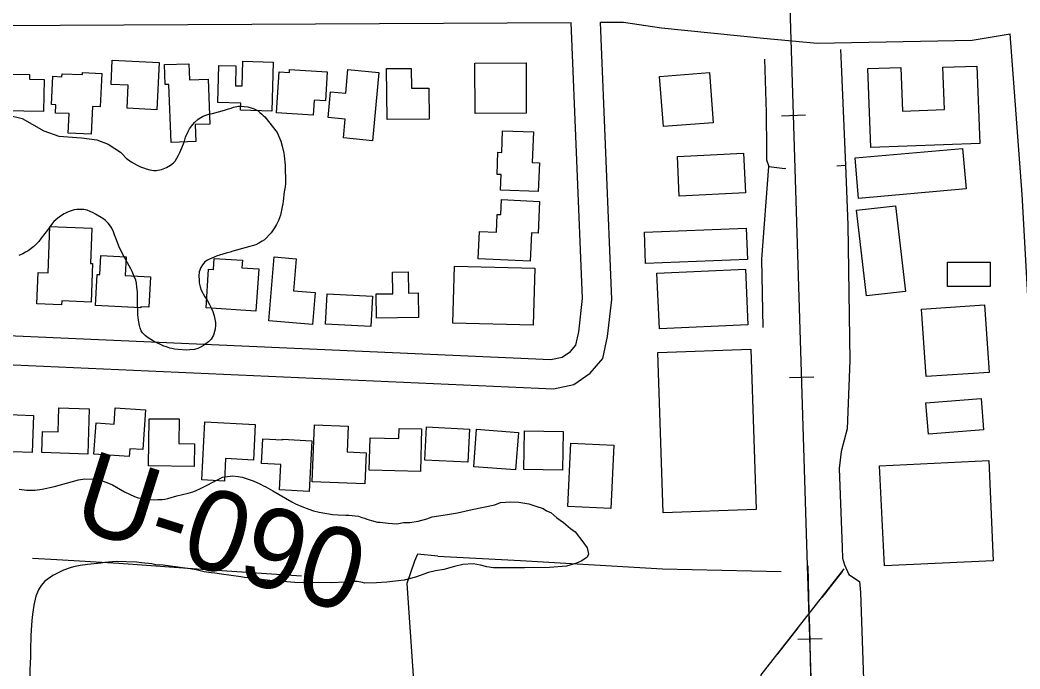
# Model space of a CAD drawing. Extents: x 3297716 to 3335574, y 688621 to 713991.
# Drawn here: x 3325465 to 3326496, y 697434 to 698103 of the extents above; entities that cross this region are included whole.
import ezdxf

# ---------------------------------------------------------------- set-up
doc = ezdxf.new("R2010")
doc.units = 0
for name, color, linetype in [('V-BLDG-OTLN', 7, 'Continuous'), ('V-RAIL-TRAK', 7, 'Continuous'), ('V-RIVR-RANG-IDEN', 7, 'Continuous'), ('V-ROAD-CNTR', 7, 'Continuous'), ('V-SITE-VEGE', 7, 'Continuous'), ('V-TOPO-SHOR', 7, 'Continuous'), ('V-UTIL-LINE', 7, 'Continuous')]:
    doc.layers.add(name, color=color, linetype=linetype)

msp = doc.modelspace()

# ---------------------------------------------------------------- linework, layer by layer
at = {"layer": 'V-BLDG-OTLN'}
for points in [[(3325559.8, 698061.9), (3325608.2, 698059.5), (3325605.8, 698010.7), (3325575, 698012.2), (3325576.1, 698035.9), (3325558.6, 698036.8)], [(3325660.3, 697995.9), (3325645.3, 697995.4), (3325645.9, 697977.8), (3325620.5, 697976.9), (3325618.2, 698036.7), (3325614.4, 698036.6), (3325613.6, 698057.2), (3325638.7, 698058.2), (3325639.4, 698041.4), (3325658.6, 698042.1)], [(3325725.6, 698059.9), (3325724.2, 698009.2), (3325692, 698010.1), (3325692.2, 698017.6), (3325668.7, 698018.3), (3325669.8, 698056.5), (3325687.3, 698056), (3325686.7, 698035.5), (3325693.7, 698035.3), (3325694.5, 698060.8)], [(3325933.8, 698058.7), (3325986.5, 698059), (3325986.8, 698007.3), (3325934.1, 698007)], [(3325548.9, 698048.1), (3325547.4, 698013.8), (3325539.3, 698014.2), (3325537.9, 697985.5), (3325514.4, 697986.5), (3325515.3, 698006.7), (3325501.1, 698007.3), (3325501.5, 698015.8), (3325497.1, 698016), (3325498.4, 698045.2), (3325507.9, 698044.8), (3325508, 698047.9), (3325528.9, 698047), (3325529, 698049)], [(3325742.6, 698052.3), (3325781.5, 698049.8), (3325779.6, 698019.9), (3325768, 698020.6), (3325767, 698005.2), (3325729.3, 698007.5), (3325732, 698049.8), (3325742.4, 698049.2)], [(3325834.7, 698049.2), (3325828, 697978.7), (3325798.1, 697981.6), (3325799.9, 698001), (3325782.4, 698002.7), (3325784.9, 698029.3), (3325800.5, 698027.8), (3325802.8, 698052.3)], [(3325868.2, 698053.4), (3325868.5, 698032.8), (3325886.3, 698033), (3325886.6, 698001), (3325843.2, 698000.5), (3325842.6, 698053.2)], [(3326124.2, 698045.1), (3326175.6, 698049.1), (3326179.7, 697997.3), (3326128.3, 697993.3)], [(3326451.4, 698055.8), (3326454.5, 697976), (3326342.3, 697971.6), (3326339.1, 698053.1), (3326373.2, 698054.4), (3326374.9, 698009.1), (3326418, 698010.8), (3326416.3, 698054.5)], [(3325488.9, 698008.8), (3325448.3, 698009.5), (3325448.4, 698018.6), (3325435.3, 698018.8), (3325435.7, 698039.7), (3325449.4, 698039.5), (3325449.5, 698047.5), (3325474.5, 698047.1), (3325474.4, 698042.1), (3325489.4, 698041.9)], [(3325999.2, 697926.5), (3325960.3, 697927.8), (3325960.9, 697943.8), (3325956.8, 697944), (3325957.6, 697966.8), (3325961.7, 697966.6), (3325962.4, 697988.9), (3325994.1, 697987.8), (3325993, 697956.3), (3326000.3, 697956)], [(3326142.6, 697962.5), (3326210.9, 697965.8), (3326212.9, 697925), (3326144.6, 697921.7)], [(3326440.4, 697929.1), (3326329.6, 697919.3), (3326325.9, 697961), (3326436.7, 697970.8)], [(3325990.7, 697854.6), (3325937.1, 697857.1), (3325938.4, 697885.3), (3325956.1, 697884.5), (3325956.9, 697902.7), (3325960.5, 697902.5), (3325961.2, 697918), (3326000.5, 697916.2), (3325999, 697883.3), (3325992, 697883.6)], [(3326337.6, 697818.8), (3326327.4, 697907.1), (3326367.7, 697911.7), (3326377.9, 697823.4)], [(3325537.9, 697812.3), (3325507.7, 697813.5), (3325507.5, 697809.4), (3325482.1, 697810.4), (3325483.4, 697842.8), (3325493.7, 697842.4), (3325495.5, 697890.2), (3325538.8, 697888.6), (3325537.4, 697852.1), (3325539.4, 697852)], [(3326108.7, 697884.5), (3326213.7, 697888.4), (3326214.9, 697856.1), (3326109.9, 697852.2)], [(3325589.1, 697806.3), (3325542.5, 697808.7), (3325544.1, 697840.8), (3325546.8, 697840.7), (3325547.8, 697860.3), (3325574.2, 697858.9), (3325573.2, 697839.7), (3325599.2, 697838.4), (3325597.6, 697807.1), (3325589.1, 697807.5)], [(3325710.8, 697846.5), (3325707.9, 697803), (3325656.5, 697806.4), (3325659.1, 697846.3), (3325664.1, 697846), (3325664.8, 697857.3), (3325694, 697855.4), (3325693.5, 697847.6)], [(3325721.2, 697793.1), (3325726.6, 697858.9), (3325749.5, 697857), (3325746.7, 697824.1), (3325768.9, 697822.2), (3325766.2, 697789.3)], [(3326465.2, 697828.4), (3326421.2, 697828.4), (3326421.2, 697853.5), (3326465.2, 697853.6)], [(3325831.8, 697820.7), (3325849.2, 697820.9), (3325848.8, 697843.2), (3325864.9, 697843.5), (3325865.3, 697821.7), (3325875.2, 697821.8), (3325875.6, 697796.6), (3325832.2, 697795.9)], [(3325912.7, 697849.5), (3325995.6, 697847.3), (3325994, 697788.4), (3325911.1, 697790.7)], [(3326121.5, 697842.2), (3326212.8, 697846.2), (3326215.3, 697788.9), (3326124.1, 697784.8)], [(3325781.4, 697820.7), (3325828.1, 697818.4), (3325826.5, 697787.2), (3325779.8, 697789.5)], [(3326464.1, 697739.8), (3326399.1, 697735.6), (3326394.5, 697805.1), (3326459.5, 697809.4)], [(3326218.3, 697763.7), (3326223.8, 697598.3), (3326127.8, 697595.1), (3326122.3, 697760.5)], [(3326458.4, 697680.5), (3326401.6, 697676), (3326399, 697708.3), (3326455.8, 697712.8)], [(3325427.7, 697697.3), (3325478.4, 697695.4), (3325477, 697657.1), (3325436.4, 697658.6), (3325436.6, 697664), (3325426.4, 697664.4)], [(3325535.9, 697702.2), (3325534.4, 697655.6), (3325487.2, 697657.1), (3325487.9, 697678.9), (3325504.1, 697678.4), (3325504.8, 697703.2)], [(3325562.9, 697703.3), (3325593.9, 697701.2), (3325591.2, 697660.2), (3325577.8, 697661.1), (3325577.2, 697653.1), (3325540.9, 697655.5), (3325543, 697687.9), (3325561.8, 697686.6)], [(3325597.1, 697643.3), (3325597.7, 697692.1), (3325628.8, 697691.8), (3325628.5, 697666.4), (3325644.5, 697666.2), (3325644.2, 697642.7)], [(3325655.2, 697688.9), (3325707.3, 697686.1), (3325705.4, 697649.4), (3325676.6, 697650.9), (3325675.4, 697627.8), (3325652, 697629.1)], [(3325766, 697627.1), (3325768.4, 697685.7), (3325803, 697684.3), (3325801.9, 697657.8), (3325821.8, 697657), (3325820.4, 697624.8)], [(3325825.6, 697672.3), (3325855.3, 697671.5), (3325855.6, 697682.1), (3325878.8, 697681.5), (3325877.7, 697637.6), (3325824.7, 697639)], [(3325883.9, 697683.6), (3325928.3, 697681.2), (3325926.5, 697647.1), (3325882.1, 697649.4)], [(3325935.6, 697681.2), (3325978.6, 697677.9), (3325975.7, 697639.2), (3325932.7, 697642.4)], [(3325985.1, 697679.7), (3326024.9, 697678.8), (3326024, 697638.9), (3325984.2, 697639.8)], [(3325765.5, 697669.1), (3325762.7, 697617.1), (3325732.1, 697618.7), (3325733.5, 697644.9), (3325713.7, 697645.9), (3325715.1, 697671.4), (3325735.2, 697670.3), (3325735.2, 697670.8)], [(3326077, 697664.9), (3326074, 697599.5), (3326029.8, 697601.5), (3326032.8, 697667)], [(3326463.7, 697648.9), (3326468.5, 697545.6), (3326356.1, 697540.3), (3326351.2, 697643.6)]]:
    msp.add_lwpolyline(points, close=True, dxfattribs=at)
at = {"layer": 'V-RAIL-TRAK'}
for points in [[(3326310.1, 696520.6), (3326277, 697540.2), (3326277, 697540.2), (3326235.8, 698858.8), (3326235.8, 698858.8), (3326142.9, 701914.3), (3326142.9, 701914.3), (3326092.1, 703411.3), (3326038.6, 704709.6), (3326038.6, 704709.6), (3326027.4, 705172.4)], [(3326277, 697540.2), (3326235.8, 698858.8)], [(3326250, 698004.5), (3326274.9, 698005.3)], [(3326258.4, 697734.6), (3326283.4, 697735.4)], [(3326266.9, 697464.7), (3326291.9, 697465.5)]]:
    msp.add_lwpolyline(points, dxfattribs=at)
msp.add_arc((3417885.5, 700007.5), 91641.7, 181.5428, 182.180572, dxfattribs=at)
at = {"layer": 'V-ROAD-CNTR'}
for points in [[(3324987.6, 698097.6), (3324943.5, 697839.1), (3324946.3, 697820.3), (3324953.2, 697804.9), (3324963, 697787.4), (3324977.9, 697774.3), (3324998, 697768.2), (3325028, 697766.8), (3325302.9, 697754.4), (3326014.7, 697722.8), (3326035.8, 697727.3), (3326052.8, 697738.9), (3326065.7, 697754.3), (3326070.6, 697776.7), (3326075, 697815), (3326063.3, 698100.9)], [(3325018, 698097.6), (3324973.9, 697838.8), (3324975.4, 697828.8), (3324980.1, 697818.4), (3324986.7, 697806.5), (3324992.8, 697801.1), (3325003.2, 697797.9), (3325029.3, 697796.8), (3325304.3, 697784.4), (3326012.2, 697753), (3326023.8, 697755.4), (3326032.5, 697761.3), (3326037.9, 697767.9), (3326040.9, 697781.6), (3326044.9, 697816.1), (3326033.2, 698100.8)], [(3325018, 698097.6), (3325439.6, 698097.6), (3326033.2, 698100.8)], [(3326063.3, 698100.9), (3326087.2, 698101.1), (3326126.1, 698095.1), (3326231.3, 698084.6), (3326286.7, 698079.2), (3326446.7, 698082.3), (3326485.9, 698089.1)], [(3327843.1, 697440.9), (3327584.8, 697467.6), (3327428.8, 697473.7), (3327369.3, 697470), (3327076.7, 697486.4), (3326863.5, 697498), (3326777.7, 697507.3), (3326552.3, 697516.7), (3326523, 697523.6), (3326507.6, 697549.9), (3326508.9, 697732.2), (3326498.3, 697923.4), (3326485.9, 698089.1)]]:
    msp.add_lwpolyline(points, dxfattribs=at)
at = {"layer": 'V-SITE-VEGE'}
for points in [[(3325452.8, 698005.2), (3325466.7, 698001.5), (3325489.2, 697988.9), (3325504.7, 697983.3), (3325528, 697981.8), (3325543.9, 697979.6), (3325555.5, 697975.3), (3325568.3, 697966.8), (3325570, 697965.4), (3325574.2, 697960.8), (3325579.3, 697957.1), (3325585.4, 697953.5), (3325588.9, 697951.9), (3325592.1, 697950.7), (3325594.8, 697949.6), (3325598.4, 697948.6), (3325602.8, 697948), (3325604.9, 697948), (3325610.5, 697949.1), (3325615.7, 697951), (3325619.7, 697953.4), (3325622.8, 697955.9), (3325624.5, 697957.8), (3325628, 697963.9), (3325629.5, 697966.6), (3325630.5, 697969), (3325633.2, 697975.7), (3325634.2, 697978.4), (3325635.4, 697982.4), (3325637.7, 697987.6), (3325639.5, 697991), (3325641.4, 697993.7), (3325644.5, 697997.5), (3325648.5, 698000.9), (3325651, 698002.6), (3325652.9, 698003.7), (3325655.1, 698004.7), (3325659.3, 698006), (3325663.1, 698006.9), (3325675.4, 698010.3), (3325677.5, 698011), (3325679.8, 698011.8), (3325682.3, 698012.5), (3325684.8, 698013.5), (3325690.1, 698014.4), (3325692.1, 698014.4), (3325699.7, 698013.6), (3325703.9, 698012.4), (3325706, 698011.6), (3325710.2, 698009.7), (3325712.1, 698007.7), (3325714, 698006.2), (3325715.5, 698004.8), (3325717.1, 698003.5)], [(3325717.1, 698003.5), (3325729.8, 697987.3), (3325733.5, 697978.3), (3325735, 697973.3), (3325736.7, 697966), (3325737.1, 697963.2), (3325738.2, 697953.4), (3325738.4, 697934.6), (3325738, 697931.2), (3325737.2, 697926.2), (3325736.2, 697916.5), (3325735.6, 697913.8), (3325735, 697910.4), (3325734.2, 697907.3), (3325733.2, 697902.1), (3325732.1, 697899.3), (3325731.5, 697897.2), (3325729.1, 697892.2), (3325727, 697888.8), (3325723.7, 697883.8), (3325716.8, 697876.6), (3325714.5, 697875.1), (3325711, 697873), (3325707.8, 697871.5), (3325698, 697868.5), (3325684.2, 697864.8), (3325681.3, 697863.8), (3325677.1, 697862.7), (3325670.4, 697860.6), (3325668.1, 697859.9), (3325665, 697858.8), (3325660, 697856.7), (3325658.1, 697855.6), (3325655.2, 697853.7), (3325652.7, 697850.8), (3325651, 697848.1), (3325649.4, 697843.6), (3325649, 697839.5), (3325649.3, 697834.8), (3325649.5, 697832.3), (3325650.4, 697828.2), (3325651.4, 697824.6), (3325655.2, 697817.9), (3325657.8, 697814.2), (3325660.1, 697810), (3325662.2, 697805.6), (3325663.5, 697802.7), (3325665, 697798.3), (3325666.1, 697791.2), (3325666.1, 697788.5), (3325665.8, 697784.5), (3325665.3, 697782), (3325664.1, 697778.2), (3325661.6, 697774), (3325658.9, 697771.5), (3325653.9, 697767.4), (3325651.6, 697766.2), (3325647.9, 697764.5), (3325644.5, 697763.6), (3325639.7, 697763.2), (3325636.4, 697762.7), (3325627.8, 697763.3), (3325623.8, 697763.7), (3325621.3, 697764.3), (3325619, 697764.7), (3325615.6, 697766.1), (3325613.1, 697766.9), (3325602.2, 697771.9), (3325595.9, 697776), (3325593.8, 697777.9), (3325591, 697780.6), (3325589.7, 697782.7), (3325588.5, 697785.6), (3325587.8, 697788.1), (3325586.7, 697793.6), (3325586.1, 697799.2), (3325586, 697805.5), (3325585.8, 697808), (3325585.7, 697822.9), (3325585.2, 697827.7), (3325584.6, 697831.9), (3325583.9, 697834.8), (3325582.4, 697838.8), (3325580.3, 697843.8), (3325579, 697846.5), (3325571.6, 697859.6), (3325567.3, 697868.2), (3325563.3, 697878.4), (3325562.2, 697881.8), (3325561.1, 697884.7), (3325559.2, 697888.6), (3325558, 697890.7), (3325555.6, 697893.6), (3325552.5, 697896.8), (3325550.2, 697898.4), (3325542.6, 697903), (3325539.9, 697904.4), (3325533.8, 697907.1), (3325530.4, 697907.7), (3325528.3, 697907.9), (3325523.3, 697907.9)], [(3325523.3, 697907.9), (3325520.6, 697907.4), (3325515.3, 697905.7), (3325512.8, 697904.6), (3325510.3, 697903.4), (3325506.4, 697901), (3325503.5, 697898.9), (3325499.5, 697895.3), (3325496, 697891.1), (3325493.9, 697887.8), (3325486.6, 697878.1), (3325483.9, 697874.7), (3325478.9, 697869.8), (3325472.9, 697865.2), (3325470.4, 697863.7), (3325467.5, 697862.2), (3325463.3, 697860.5)], [(3325463.7, 697619.5), (3325471.4, 697618.3), (3325479.8, 697618.4), (3325487.6, 697619.5), (3325500.3, 697622), (3325524.8, 697629.1), (3325531.3, 697630.2), (3325542.8, 697629.8), (3325548.8, 697628.2), (3325557.5, 697624.9), (3325560.1, 697623.7), (3325572.3, 697616.7), (3325582.6, 697611.7), (3325586.4, 697610.6), (3325588.9, 697610.1), (3325596.9, 697608.9), (3325603, 697608.5), (3325606.6, 697608.6), (3325611.1, 697608.8), (3325613.9, 697609.2), (3325617.1, 697609.9), (3325626.2, 697612.4), (3325638.2, 697615.3), (3325642.9, 697616.8), (3325645.6, 697617.8), (3325651.6, 697620.4), (3325658.3, 697623.7), (3325662.7, 697626.1), (3325665.7, 697627.6), (3325671, 697630.5), (3325673.5, 697631.6), (3325681.5, 697632.9), (3325683.7, 697633), (3325689.7, 697632.5), (3325693.7, 697631.9), (3325705.2, 697628), (3325712, 697624.8), (3325715.8, 697622.8), (3325718.3, 697621.7), (3325725.5, 697617.8), (3325744.8, 697606.3), (3325748.8, 697604.3), (3325755.4, 697601.5), (3325762.5, 697598.6), (3325767.3, 697597.2), (3325773.1, 697595.6), (3325786.8, 697593.3), (3325792.8, 697592.8), (3325800.8, 697592.5), (3325803.9, 697592.5)], [(3325803.9, 697592.5), (3325813.7, 697591.4), (3325817.3, 697590.2), (3325819.8, 697589.6), (3325822.2, 697588.4), (3325827.1, 697587.2), (3325833.2, 697585.4), (3325836.2, 697585.4), (3325844.2, 697584.3), (3325853.3, 697583.7), (3325860, 697585), (3325866.7, 697585.1), (3325875.2, 697586.3), (3325884.3, 697588.8), (3325889.8, 697590.7), (3325905.6, 697593.2), (3325915.9, 697595.1), (3325931.1, 697598.3), (3325954.2, 697603.3), (3325960.3, 697605.8), (3325970.6, 697606.5), (3325979.1, 697606), (3325989.5, 697604.2), (3325996.8, 697601.8), (3326004.2, 697599.4), (3326007.8, 697597), (3326012.1, 697595.2), (3326018.2, 697589.8), (3326025, 697585), (3326032.3, 697579), (3326037.2, 697575.3), (3326045.2, 697565), (3326049.5, 697559), (3326050.8, 697552.3), (3326049.6, 697549.2), (3326044.1, 697545.6), (3326038.7, 697543.1), (3326028.3, 697540), (3326010.7, 697538.6), (3325985.1, 697538.4), (3325961.4, 697538.3), (3325952.9, 697538.2), (3325946.1, 697539.4), (3325939.4, 697541.1), (3325932.1, 697542.3), (3325921.2, 697541.6), (3325912.7, 697539.7), (3325901.7, 697536.6), (3325893.2, 697535.3), (3325885.9, 697533.4), (3325872.6, 697528.5), (3325861, 697525.4), (3325842.8, 697523.4), (3325832.4, 697522.7), (3325820.3, 697522.6), (3325817.8, 697523.2), (3325812.2, 697524.2), (3325808.9, 697524.2), (3325799.6, 697523.4), (3325786.2, 697522.8), (3325748, 697523.2), (3325735.8, 697524), (3325725.1, 697525), (3325699.7, 697527.8), (3325696.1, 697528.3), (3325692.5, 697529), (3325672.3, 697531.6), (3325665.7, 697532.6), (3325661.7, 697533.1), (3325654.6, 697534.3), (3325646.2, 697536.1), (3325640, 697537.2), (3325637.5, 697537.7), (3325617.4, 697540.4), (3325614.4, 697540.6), (3325612.4, 697541), (3325604.7, 697541.4), (3325600.7, 697542.3), (3325589.8, 697543.3), (3325584.7, 697544), (3325563.8, 697544.8), (3325552, 697543.8), (3325547.8, 697543.2), (3325534.3, 697541.8), (3325526.7, 697540.5), (3325519.8, 697539.2), (3325516.3, 697538.3), (3325509.3, 697535.8), (3325498.4, 697530.5), (3325490.3, 697524.4), (3325486.5, 697520.2), (3325483.6, 697515.7), (3325481.1, 697509.1), (3325479, 697499.8), (3325477.9, 697492.7), (3325477.2, 697487.4), (3325476.4, 697479.4), (3325475.7, 697468.1), (3325475.3, 697453.8), (3325475.4, 697445.8), (3325475, 697440.5)], [(3325475, 697440.5), (3325474.7, 697432.5), (3325474.8, 697425.2), (3325474.4, 697409.2), (3325473.7, 697392.5), (3325472.5, 697367.3), (3325472.1, 697363.3), (3325471.6, 697359.2), (3325471.5, 697355), (3325471, 697349.1), (3325471, 697343.5), (3325470.7, 697340.2), (3325470.5, 697337.3), (3325470.5, 697333.3), (3325470.2, 697330.6), (3325470.2, 697327.3), (3325469.7, 697320.6), (3325469.4, 697318.6), (3325469, 697315.7), (3325467.3, 697310.4), (3325464.9, 697308.9), (3325462.5, 697308.2)]]:
    msp.add_lwpolyline(points, dxfattribs=at)
at = {"layer": 'V-TOPO-SHOR'}
msp.add_line((3326307.2, 697952.9), (3326316, 697953.4), dxfattribs=at)
for points in [[(3326311, 698073), (3326311.7, 698057.6), (3326316, 697953.4), (3326318.6, 697892), (3326320.5, 697752.2), (3326317.8, 697681.7), (3326311.5, 697658.2), (3326309.4, 697640.7), (3326312.7, 697559.1), (3326312.9, 697548.1), (3326315.1, 697541.2), (3326319.6, 697531.3), (3326330.5, 697524), (3326331.5, 697512.9), (3326335.2, 697403.2)], [(3326232.5, 698062.7), (3326234.2, 698007.9), (3326234.5, 697969.2), (3326234.4, 697958.9), (3326237, 697952.3), (3326253.4, 697950.2), (3326254.6, 697950.3)], [(3326231, 697786), (3326229.9, 697856.6), (3326237, 697952.3)], [(3325754.9, 697529.8), (3325652, 697536.4), (3325566.7, 697542.7), (3325502.5, 697546.6), (3325477.5, 697547.8)], [(3325895.4, 697550.4), (3325874.6, 697552.3), (3325871.6, 697545.3), (3325863.5, 697522.1), (3325872.1, 697396.9), (3325869.7, 697148.2), (3325861.7, 696912.2), (3325856.2, 696596.2), (3325850.3, 696323.1), (3325844.9, 696097.8), (3325846, 696045)], [(3325895.4, 697550.4), (3325980.7, 697545.8), (3326127.4, 697537.1), (3326249.7, 697534.6)]]:
    msp.add_lwpolyline(points, dxfattribs=at)
at = {"layer": 'V-UTIL-LINE'}
for points in [[(3326949.7, 694025), (3326797, 694337.7), (3326660.2, 694658.1), (3326506.4, 695114.6), (3326396.2, 695554.3), (3326308.7, 696045.9), (3326267.3, 696515.1), (3326247.1, 696982.5), (3326229.2, 697428), (3326314.7, 697537.1)], [(3326291.8, 697507.8), (3326312.8, 697534.5)], [(3326246.1, 697449.5), (3326267.1, 697476.3)]]:
    msp.add_lwpolyline(points, dxfattribs=at)

# ---------------------------------------------------------------- texts
at = {"layer": 'V-RIVR-RANG-IDEN'}
msp.add_text('U-090', height=83, rotation=342.5273, dxfattribs=at).set_placement((3325515.4, 697581.1))

doc.saveas('drawing.dxf')
